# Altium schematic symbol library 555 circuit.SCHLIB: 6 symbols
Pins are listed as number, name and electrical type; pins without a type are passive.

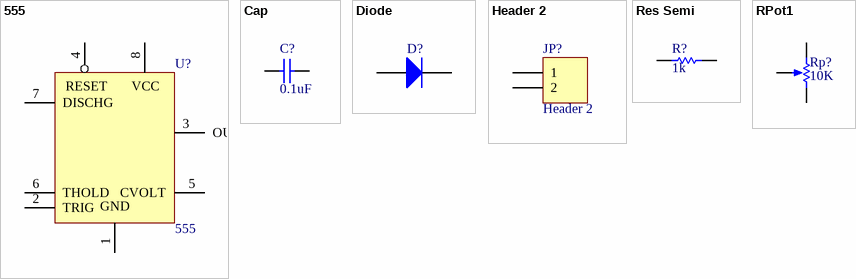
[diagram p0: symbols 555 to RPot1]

## 555
designator U?
Timer
simulation model 555 (SUBCKT)
pins: 1 GND, 2 TRIG, 3 OUT, 4 RESET, 5 CVOLT, 6 THOLD, 7 DISCHG, 8 VCC

## Cap
designator C?, comment 0.1uF
Capacitor; Manufacturer: Generic Components; Class I: Passive
footprint RAD-0.3
simulation model CAP (Capacitor)
signal-integrity model Cap
pins: 1, 2

## Diode
designator D?
Default Diode; Manufacturer: Generic Components; Class I: Discrete; Class II: Diode - Switching
footprint DSO-C2/X3.3 (DO-214AB)
simulation model DIODE (Diode)
signal-integrity model Diode
pins: 1 A, 2 K

## Header 2
designator JP?
Header, 2-Pin; Manufacturer: Generic Components; Class I: Connector
footprint HDR1X2
signal-integrity model Connector
pins: 1, 2

## Res Semi
designator R?, comment 1k
Semiconductor Resistor; Manufacturer: Generic Components; Class I: Passive
footprint AXIAL-0.5
simulation model RES (Semiconductor Resistor)
signal-integrity model Res Semi
pins: 1, 2

## RPot1
designator Rp?  value 10K
Potentiometer; Manufacturer: Generic Components; Class I: Passive; Set Position: 0.5
footprint VR5
simulation model POT (Potentiometer)
pins: 1 TOP, 2 BOT, 3 TAP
